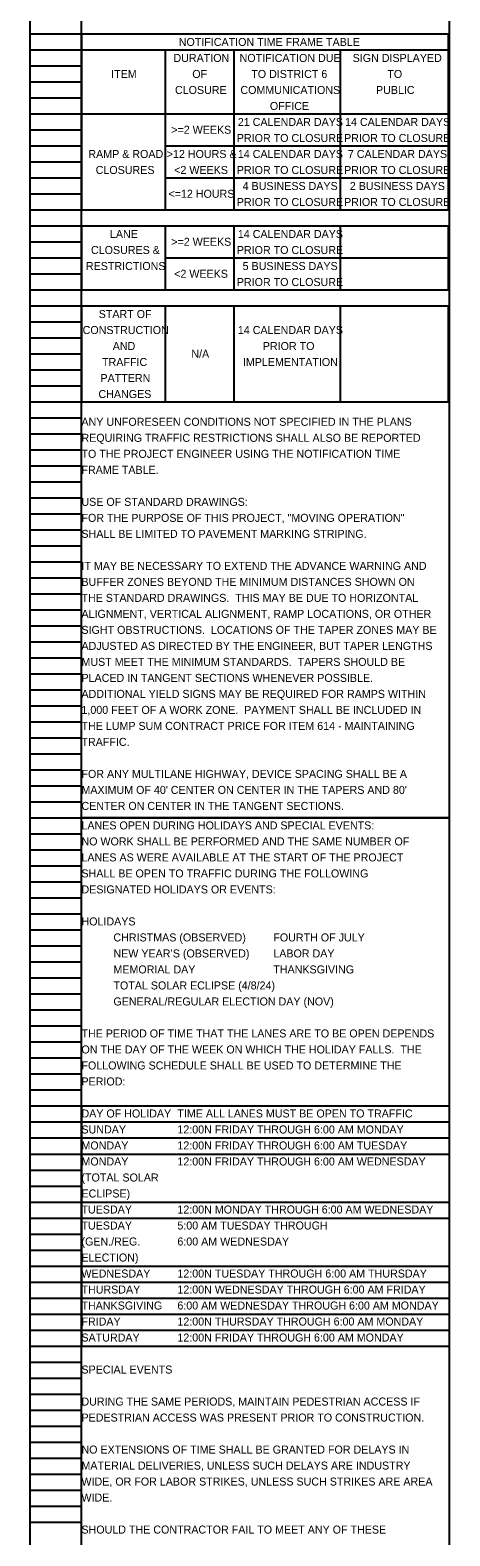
# Model space of a CAD drawing. Extents: x 16463 to 16500, y 5400 to 5823.
# Drawn here: x 16463.05 to 16470.4, y 5770.59 to 5796.94 of the extents above; entities that cross this region are included whole.
import ezdxf

# ---------------------------------------------------------------- set-up
doc = ezdxf.new("R2010")
doc.units = 0
for name, color, linetype in [('Default', 7, 'Continuous'), ('SC_Scratch1', 7, 'Continuous'), ('SH_Data', 7, 'Continuous'), ('SH_Text', 7, 'Continuous')]:
    doc.layers.add(name, color=color, linetype=linetype)

msp = doc.modelspace()

# ---------------------------------------------------------------- linework, layer by layer
at = {"layer": 'Default'}
for p, q in [((16463.949, 5778.112), (16470.389, 5778.112)), ((16463.949, 5777.832), (16470.389, 5777.832)), ((16463.949, 5777.552), (16470.389, 5777.552)), ((16463.949, 5777.272), (16470.389, 5777.272)), ((16463.949, 5776.432), (16470.389, 5776.432)), ((16463.949, 5776.152), (16470.389, 5776.152)), ((16463.949, 5775.312), (16470.389, 5775.312)), ((16463.949, 5775.032), (16470.389, 5775.032)), ((16463.949, 5774.752), (16470.389, 5774.752)), ((16463.949, 5774.472), (16470.389, 5774.472)), ((16463.949, 5774.192), (16470.389, 5774.192))]:
    msp.add_line(p, q, dxfattribs=at)
for points in [[(16463.949, 5778.112), (16463.949, 5773.912), (16470.389, 5773.912)], [(16463.949, 5778.112), (16470.389, 5778.112), (16470.389, 5773.912)]]:
    msp.add_lwpolyline(points, dxfattribs=at)
at = {"layer": 'SC_Scratch1'}
for points in [[(16463.949, 5803.312), (16470.389, 5803.312), (16470.389, 5783.152), (16463.949, 5783.152)], [(16463.949, 5783.152), (16470.389, 5783.152), (16470.389, 5762.992), (16463.949, 5762.992)]]:
    msp.add_lwpolyline(points, close=True, dxfattribs=at)
at = {"layer": 'SH_Data'}
for p, q in [((16463.049, 5783.152), (16463.049, 5803.312)), ((16463.949, 5783.152), (16463.949, 5803.312)), ((16463.049, 5796.872), (16463.949, 5796.872)), ((16463.949, 5796.872), (16470.373, 5796.872)), ((16463.949, 5796.872), (16463.949, 5793.792)), ((16470.373, 5796.872), (16470.373, 5793.792)), ((16463.049, 5796.592), (16463.949, 5796.592)), ((16463.949, 5796.592), (16470.373, 5796.592)), ((16465.415, 5796.592), (16465.415, 5793.792)), ((16466.618, 5796.592), (16466.618, 5793.792)), ((16468.479, 5796.592), (16468.479, 5793.792)), ((16463.049, 5796.312), (16463.949, 5796.312)), ((16463.049, 5796.032), (16463.949, 5796.032)), ((16463.049, 5795.752), (16463.949, 5795.752)), ((16463.049, 5795.472), (16463.949, 5795.472)), ((16463.949, 5795.472), (16470.373, 5795.472)), ((16463.049, 5795.192), (16463.949, 5795.192)), ((16463.049, 5794.912), (16463.949, 5794.912)), ((16465.415, 5794.912), (16470.373, 5794.912)), ((16463.049, 5794.632), (16463.949, 5794.632)), ((16463.049, 5794.352), (16463.949, 5794.352)), ((16465.415, 5794.352), (16470.373, 5794.352)), ((16463.049, 5794.072), (16463.949, 5794.072)), ((16463.049, 5793.792), (16463.949, 5793.792)), ((16463.949, 5793.792), (16470.373, 5793.792)), ((16463.049, 5793.512), (16463.949, 5793.512)), ((16463.949, 5793.512), (16470.373, 5793.512)), ((16463.949, 5793.512), (16463.949, 5792.392)), ((16465.415, 5793.512), (16465.415, 5792.392)), ((16466.618, 5793.512), (16466.618, 5792.392)), ((16468.479, 5793.512), (16468.479, 5792.392)), ((16470.373, 5793.512), (16470.373, 5792.392)), ((16463.049, 5793.232), (16463.949, 5793.232)), ((16463.049, 5792.952), (16463.949, 5792.952)), ((16465.415, 5792.952), (16470.373, 5792.952)), ((16463.049, 5792.672), (16463.949, 5792.672)), ((16463.049, 5792.392), (16463.949, 5792.392)), ((16463.949, 5792.392), (16470.373, 5792.392)), ((16463.049, 5792.112), (16463.949, 5792.112)), ((16463.949, 5792.112), (16470.373, 5792.112)), ((16463.949, 5792.112), (16463.949, 5790.432)), ((16465.415, 5792.112), (16465.415, 5790.432)), ((16466.618, 5792.112), (16466.618, 5790.432)), ((16468.479, 5792.112), (16468.479, 5790.432)), ((16470.373, 5792.112), (16470.373, 5790.432)), ((16463.049, 5791.832), (16463.949, 5791.832)), ((16463.049, 5791.552), (16463.949, 5791.552)), ((16463.049, 5791.272), (16463.949, 5791.272)), ((16463.049, 5790.992), (16463.949, 5790.992)), ((16463.049, 5790.712), (16463.949, 5790.712)), ((16463.049, 5790.432), (16463.949, 5790.432)), ((16463.949, 5790.432), (16470.373, 5790.432)), ((16463.049, 5790.152), (16463.949, 5790.152)), ((16463.049, 5789.872), (16463.949, 5789.872)), ((16463.049, 5789.592), (16463.949, 5789.592)), ((16463.049, 5789.312), (16463.949, 5789.312)), ((16463.049, 5789.032), (16463.949, 5789.032)), ((16463.049, 5788.752), (16463.949, 5788.752)), ((16463.049, 5788.472), (16463.949, 5788.472)), ((16463.049, 5788.192), (16463.949, 5788.192)), ((16463.049, 5787.912), (16463.949, 5787.912)), ((16463.049, 5787.632), (16463.949, 5787.632)), ((16463.049, 5787.352), (16463.949, 5787.352)), ((16463.049, 5787.072), (16463.949, 5787.072)), ((16463.049, 5786.792), (16463.949, 5786.792)), ((16463.049, 5786.512), (16463.949, 5786.512)), ((16463.049, 5786.232), (16463.949, 5786.232)), ((16463.049, 5785.952), (16463.949, 5785.952)), ((16463.049, 5785.672), (16463.949, 5785.672)), ((16463.049, 5785.392), (16463.949, 5785.392)), ((16463.049, 5785.112), (16463.949, 5785.112)), ((16463.049, 5784.832), (16463.949, 5784.832)), ((16463.049, 5784.552), (16463.949, 5784.552)), ((16463.049, 5784.272), (16463.949, 5784.272)), ((16463.049, 5783.992), (16463.949, 5783.992)), ((16463.049, 5783.712), (16463.949, 5783.712)), ((16463.049, 5783.432), (16463.949, 5783.432)), ((16463.049, 5762.992), (16463.049, 5783.152)), ((16463.049, 5783.152), (16463.949, 5783.152)), ((16463.049, 5783.152), (16463.949, 5783.152)), ((16463.949, 5762.992), (16463.949, 5783.152)), ((16463.049, 5782.872), (16463.949, 5782.872)), ((16463.049, 5782.592), (16463.949, 5782.592)), ((16463.049, 5782.312), (16463.949, 5782.312)), ((16463.049, 5782.032), (16463.949, 5782.032)), ((16463.049, 5781.752), (16463.949, 5781.752)), ((16463.049, 5781.472), (16463.949, 5781.472)), ((16463.049, 5781.192), (16463.949, 5781.192)), ((16463.049, 5780.912), (16463.949, 5780.912)), ((16463.049, 5780.632), (16463.949, 5780.632)), ((16463.049, 5780.352), (16463.949, 5780.352)), ((16463.049, 5780.072), (16463.949, 5780.072)), ((16463.049, 5779.792), (16463.949, 5779.792)), ((16463.049, 5779.512), (16463.949, 5779.512)), ((16463.049, 5779.232), (16463.949, 5779.232)), ((16463.049, 5778.952), (16463.949, 5778.952)), ((16463.049, 5778.672), (16463.949, 5778.672)), ((16463.049, 5778.392), (16463.949, 5778.392)), ((16463.049, 5778.112), (16463.949, 5778.112)), ((16463.049, 5777.832), (16463.949, 5777.832)), ((16463.049, 5777.552), (16463.949, 5777.552)), ((16463.049, 5777.272), (16463.949, 5777.272)), ((16463.049, 5776.992), (16463.949, 5776.992)), ((16463.049, 5776.712), (16463.949, 5776.712)), ((16463.049, 5776.432), (16463.949, 5776.432)), ((16463.049, 5776.152), (16463.949, 5776.152)), ((16463.049, 5775.872), (16463.949, 5775.872)), ((16463.049, 5775.592), (16463.949, 5775.592)), ((16463.049, 5775.312), (16463.949, 5775.312)), ((16463.049, 5775.032), (16463.949, 5775.032)), ((16463.049, 5774.752), (16463.949, 5774.752)), ((16463.049, 5774.472), (16463.949, 5774.472)), ((16463.049, 5774.192), (16463.949, 5774.192)), ((16463.049, 5773.912), (16463.949, 5773.912)), ((16463.049, 5773.632), (16463.949, 5773.632)), ((16463.049, 5773.352), (16463.949, 5773.352)), ((16463.049, 5773.072), (16463.949, 5773.072)), ((16463.049, 5772.792), (16463.949, 5772.792)), ((16463.049, 5772.512), (16463.949, 5772.512)), ((16463.049, 5772.232), (16463.949, 5772.232)), ((16463.049, 5771.952), (16463.949, 5771.952)), ((16463.049, 5771.672), (16463.949, 5771.672)), ((16463.049, 5771.392), (16463.949, 5771.392)), ((16463.049, 5771.112), (16463.949, 5771.112)), ((16463.049, 5770.832), (16463.949, 5770.832))]:
    msp.add_line(p, q, dxfattribs=at)

# ---------------------------------------------------------------- texts
at = {"layer": 'Default'}
for s, p in [('LANES OPEN DURING HOLIDAYS AND SPECIAL EVENTS:', (16463.949, 5782.951)), ('NO WORK SHALL BE PERFORMED AND THE SAME NUMBER OF ', (16463.949, 5782.671)), ('LANES AS WERE AVAILABLE AT THE START OF THE PROJECT ', (16463.949, 5782.391)), ('SHALL BE OPEN TO TRAFFIC DURING THE FOLLOWING ', (16463.949, 5782.111)), ('DESIGNATED HOLIDAYS OR EVENTS:', (16463.949, 5781.831)), ('HOLIDAYS', (16463.949, 5781.271)), ('CHRISTMAS (OBSERVED)', (16464.509, 5780.991)), ('FOURTH OF JULY', (16467.309, 5780.991)), ('NEW YEAR’S (OBSERVED)', (16464.509, 5780.711)), ('LABOR DAY', (16467.309, 5780.711)), ('MEMORIAL DAY          ', (16464.509, 5780.431)), ('THANKSGIVING', (16467.309, 5780.431)), ('TOTAL SOLAR ECLIPSE (4/8/24)', (16464.509, 5780.151)), ('GENERAL/REGULAR ELECTION DAY (NOV)', (16464.509, 5779.871)), ('THE PERIOD OF TIME THAT THE LANES ARE TO BE OPEN DEPENDS ', (16463.949, 5779.311)), ('ON THE DAY OF THE WEEK ON WHICH THE HOLIDAY FALLS.  THE ', (16463.949, 5779.031)), ('FOLLOWING SCHEDULE SHALL BE USED TO DETERMINE THE ', (16463.949, 5778.751)), ('PERIOD:', (16463.949, 5778.471)), ('DAY OF HOLIDAY', (16463.949, 5777.911)), ('TIME ALL LANES MUST BE OPEN TO TRAFFIC', (16465.629, 5777.911)), ('SUNDAY', (16463.949, 5777.631)), ('12:00N FRIDAY THROUGH 6:00 AM MONDAY', (16465.629, 5777.631)), ('MONDAY', (16463.949, 5777.351)), ('12:00N FRIDAY THROUGH 6:00 AM TUESDAY', (16465.629, 5777.351)), ('MONDAY', (16463.949, 5777.071)), ('12:00N FRIDAY THROUGH 6:00 AM WEDNESDAY', (16465.629, 5777.071)), ('(TOTAL SOLAR ', (16463.949, 5776.791)), ('ECLIPSE)', (16463.949, 5776.511)), ('TUESDAY', (16463.949, 5776.231)), ('12:00N MONDAY THROUGH 6:00 AM WEDNESDAY', (16465.629, 5776.231)), ('TUESDAY', (16463.949, 5775.951)), ('5:00 AM TUESDAY THROUGH  ', (16465.629, 5775.951)), ('(GEN./REG.', (16463.949, 5775.671)), ('6:00 AM WEDNESDAY', (16465.629, 5775.671)), ('ELECTION)', (16463.949, 5775.391)), ('WEDNESDAY', (16463.949, 5775.111)), ('12:00N TUESDAY THROUGH 6:00 AM THURSDAY', (16465.629, 5775.111)), ('THURSDAY', (16463.949, 5774.831)), ('12:00N WEDNESDAY THROUGH 6:00 AM FRIDAY', (16465.629, 5774.831)), ('THANKSGIVING', (16463.949, 5774.551)), ('6:00 AM WEDNESDAY THROUGH 6:00 AM MONDAY', (16465.629, 5774.551)), ('FRIDAY', (16463.949, 5774.271)), ('12:00N THURSDAY THROUGH 6:00 AM MONDAY', (16465.629, 5774.271)), ('SATURDAY', (16463.949, 5773.991)), ('12:00N FRIDAY THROUGH 6:00 AM MONDAY', (16465.629, 5773.991)), ('SPECIAL EVENTS', (16463.949, 5773.431)), ('DURING THE SAME PERIODS, MAINTAIN PEDESTRIAN ACCESS IF ', (16463.949, 5772.871)), ('PEDESTRIAN ACCESS WAS PRESENT PRIOR TO CONSTRUCTION.', (16463.949, 5772.591)), ('NO EXTENSIONS OF TIME SHALL BE GRANTED FOR DELAYS IN ', (16463.949, 5772.031)), ('MATERIAL DELIVERIES, UNLESS SUCH DELAYS ARE INDUSTRY ', (16463.949, 5771.751)), ('WIDE, OR FOR LABOR STRIKES, UNLESS SUCH STRIKES ARE AREA ', (16463.949, 5771.471)), ('WIDE.', (16463.949, 5771.191)), ('SHOULD THE CONTRACTOR FAIL TO MEET ANY OF THESE ', (16463.949, 5770.631))]:
    msp.add_text(s, height=0.14, dxfattribs=at).set_placement(p)
at = {"layer": 'SH_Data'}
for s, p in [('NOTIFICATION TIME FRAME TABLE', (16465.653, 5796.658)), ('DURATION', (16465.56, 5796.378)), ('NOTIFICATION DUE', (16466.719, 5796.378)), ('SIGN DISPLAYED', (16468.699, 5796.378)), ('ITEM', (16464.469, 5796.098)), ('OF', (16465.89, 5796.098)), ('TO DISTRICT 6', (16466.923, 5796.098)), ('TO', (16469.306, 5796.098)), ('CLOSURE', (16465.587, 5795.818)), ('COMMUNICATIONS', (16466.733, 5795.818)), ('PUBLIC', (16469.107, 5795.818)), (' OFFICE', (16467.197, 5795.538)), ('>=2 WEEKS', (16465.522, 5795.122)), ('21 CALENDAR DAYS', (16466.688, 5795.258)), ('14 CALENDAR DAYS', (16468.566, 5795.258)), ('PRIOR TO CLOSURE', (16466.67, 5794.978)), ('PRIOR TO CLOSURE', (16468.548, 5794.978)), ('RAMP & ROAD', (16464.07, 5794.698)), ('>12 HOURS &', (16465.443, 5794.698)), ('14 CALENDAR DAYS', (16466.688, 5794.698)), ('7 CALENDAR DAYS', (16468.615, 5794.698)), ('CLOSURES', (16464.198, 5794.418)), ('<2 WEEKS', (16465.573, 5794.418)), ('PRIOR TO CLOSURE', (16466.67, 5794.418)), ('PRIOR TO CLOSURE', (16468.548, 5794.418)), ('4 BUSINESS DAYS', (16466.772, 5794.138)), ('2 BUSINESS DAYS', (16468.649, 5794.138)), ('<=12 HOURS', (16465.473, 5794.002)), ('PRIOR TO CLOSURE', (16466.67, 5793.858)), ('PRIOR TO CLOSURE', (16468.548, 5793.858)), ('LANE', (16464.448, 5793.298)), ('14 CALENDAR DAYS', (16466.688, 5793.298)), ('CLOSURES &', (16464.116, 5793.018)), ('>=2 WEEKS', (16465.522, 5793.162)), ('PRIOR TO CLOSURE', (16466.67, 5793.018)), ('RESTRICTIONS', (16464.027, 5792.738)), ('5 BUSINESS DAYS', (16466.772, 5792.738)), ('<2 WEEKS', (16465.573, 5792.602)), ('PRIOR TO CLOSURE', (16466.67, 5792.458)), ('START OF', (16464.251, 5791.898)), ('CONSTRUCTION', (16463.97, 5791.618)), ('14 CALENDAR DAYS', (16466.688, 5791.618)), ('AND', (16464.497, 5791.338)), ('N/A', (16465.874, 5791.202)), ('PRIOR TO', (16467.125, 5791.338)), ('TRAFFIC', (16464.31, 5791.058)), ('IMPLEMENTATION', (16466.776, 5791.058)), ('PATTERN', (16464.282, 5790.778)), ('CHANGES', (16464.247, 5790.498))]:
    msp.add_text(s, height=0.14, dxfattribs=at).set_placement(p)
at = {"layer": 'SH_Text'}
for s, p in [('ANY UNFORESEEN CONDITIONS NOT SPECIFIED IN THE PLANS ', (16463.949, 5790.012)), ('REQUIRING TRAFFIC RESTRICTIONS SHALL ALSO BE REPORTED ', (16463.949, 5789.732)), ('TO THE PROJECT ENGINEER USING THE NOTIFICATION TIME ', (16463.949, 5789.452)), ('FRAME TABLE. ', (16463.949, 5789.172)), ('USE OF STANDARD DRAWINGS:', (16463.949, 5788.612)), ('FOR THE PURPOSE OF THIS PROJECT, "MOVING OPERATION" ', (16463.949, 5788.332)), ('SHALL BE LIMITED TO PAVEMENT MARKING STRIPING.', (16463.949, 5788.052)), ('IT MAY BE NECESSARY TO EXTEND THE ADVANCE WARNING AND ', (16463.949, 5787.492)), ('BUFFER ZONES BEYOND THE MINIMUM DISTANCES SHOWN ON ', (16463.949, 5787.212)), ('THE STANDARD DRAWINGS.  THIS MAY BE DUE TO HORIZONTAL ', (16463.949, 5786.932)), ('ALIGNMENT, VERTICAL ALIGNMENT, RAMP LOCATIONS, OR OTHER ', (16463.949, 5786.652)), ('SIGHT OBSTRUCTIONS.  LOCATIONS OF THE TAPER ZONES MAY BE ', (16463.949, 5786.372)), ('ADJUSTED AS DIRECTED BY THE ENGINEER, BUT TAPER LENGTHS ', (16463.949, 5786.092)), ('MUST MEET THE MINIMUM STANDARDS.  TAPERS SHOULD BE ', (16463.949, 5785.812)), ('PLACED IN TANGENT SECTIONS WHENEVER POSSIBLE.  ', (16463.949, 5785.532)), ('ADDITIONAL YIELD SIGNS MAY BE REQUIRED FOR RAMPS WITHIN ', (16463.949, 5785.252)), ('1,000 FEET OF A WORK ZONE.  PAYMENT SHALL BE INCLUDED IN ', (16463.949, 5784.972)), ('THE LUMP SUM CONTRACT PRICE FOR ITEM 614 - MAINTAINING ', (16463.949, 5784.692)), ('TRAFFIC.', (16463.949, 5784.412)), ('FOR ANY MULTILANE HIGHWAY, DEVICE SPACING SHALL BE A ', (16463.949, 5783.852)), ("MAXIMUM OF 40' CENTER ON CENTER IN THE TAPERS AND 80' ", (16463.949, 5783.572)), ('CENTER ON CENTER IN THE TANGENT SECTIONS.', (16463.949, 5783.292))]:
    msp.add_text(s, height=0.14, dxfattribs=at).set_placement(p)

doc.saveas('drawing.dxf')
